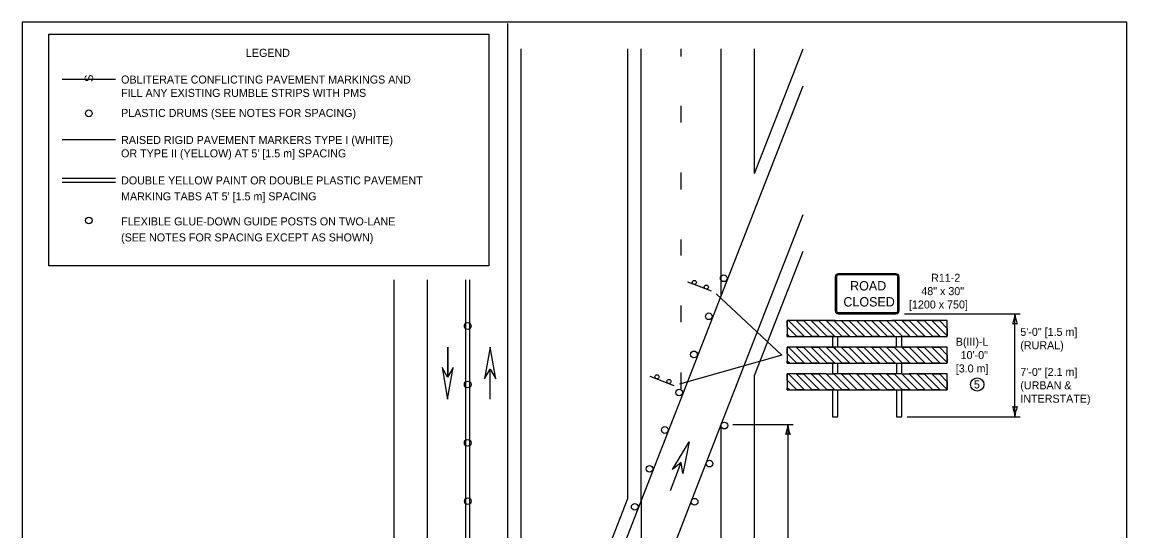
# Model space of a CAD drawing. Extents: x 49991.4 to 50021, y 49987.6 to 50011.4.
# Drawn here: x 50000.34 to 50008.61, y 50007.45 to 50011.26 of the extents above; entities that cross this region are included whole.
import ezdxf

# ---------------------------------------------------------------- set-up
doc = ezdxf.new("R2010")
doc.units = 0
for name, color, linetype in [('Level 1', 7, 'Continuous'), ('Level 2', 7, 'Continuous'), ('Level 3', 7, 'Continuous')]:
    doc.layers.add(name, color=color, linetype=linetype)

msp = doc.modelspace()

# ---------------------------------------------------------------- linework, layer by layer
at = {"layer": 'Level 1'}
for p, q in [((50003.9747, 50005.1129), (50003.9747, 50011.2528)), ((50004.0747, 50005.6442), (50004.0747, 50011.0628)), ((50004.8747, 50007.6956), (50004.8747, 50011.0628)), ((50004.9747, 50007.6763), (50004.9747, 50011.0628)), ((50005.2747, 50011.0059), (50005.2747, 50011.0628)), ((50005.5747, 50009.2143), (50005.5747, 50011.0628)), ((50005.8247, 50010.1303), (50005.8247, 50011.0628)), ((50005.8247, 50010.1303), (50006.1881, 50011.0617)), ((50001.0367, 50010.8335), (50000.6356, 50010.8335)), ((50005.5747, 50009.2143), (50006.1881, 50010.7865)), ((50005.2747, 50010.5108), (50005.2747, 50010.6358)), ((50001.0367, 50010.3818), (50000.6356, 50010.3818)), ((50005.2747, 50010.0108), (50005.2747, 50010.1358)), ((50001.0367, 50010.0915), (50000.6356, 50010.0915)), ((50001.0367, 50010.0615), (50000.6356, 50010.0615)), ((50005.5747, 50008.2511), (50006.1881, 50009.8235)), ((50005.2747, 50009.5158), (50005.2747, 50009.6358)), ((50005.8247, 50008.6168), (50006.1881, 50009.5483)), ((50003.1247, 50002.2265), (50003.1247, 50009.3328)), ((50003.3747, 50002.2265), (50003.3747, 50009.3328)), ((50003.6597, 50002.2708), (50003.6597, 50009.3328)), ((50003.6897, 50002.1862), (50003.6897, 50009.3328)), ((50005.4127, 50009.2823), (50005.3233, 50009.3171)), ((50006.4286, 50009.3563), (50006.4286, 50009.1013)), ((50006.4386, 50009.3563), (50006.4386, 50009.1013)), ((50006.8836, 50009.3788), (50006.4536, 50009.3788)), ((50006.8836, 50009.3698), (50006.4536, 50009.3698)), ((50006.8986, 50009.1013), (50006.8986, 50009.3563)), ((50006.9086, 50009.1013), (50006.9086, 50009.3563)), ((50005.5022, 50009.2474), (50005.4127, 50009.2823)), ((50003.9747, 50005.1129), (50005.5747, 50009.2143)), ((50005.2747, 50009.0158), (50005.2747, 50009.1408)), ((50006.4536, 50009.0878), (50006.8836, 50009.0878)), ((50006.4536, 50009.0788), (50006.8836, 50009.0788)), ((50006.1419, 50008.9088), (50006.0686, 50008.9821)), ((50006.1419, 50008.9088), (50006.0686, 50008.9821)), ((50006.1984, 50008.9088), (50006.0784, 50009.0288)), ((50006.0784, 50009.0288), (50006.1984, 50008.9088)), ((50006.255, 50008.9088), (50006.135, 50009.0288)), ((50006.255, 50008.9088), (50006.135, 50009.0288)), ((50006.3116, 50008.9088), (50006.1916, 50009.0288)), ((50006.1916, 50009.0288), (50006.3116, 50008.9088)), ((50006.3681, 50008.9088), (50006.2481, 50009.0288)), ((50006.3681, 50008.9088), (50006.2481, 50009.0288)), ((50006.4247, 50008.9088), (50006.3047, 50009.0288)), ((50006.3047, 50009.0288), (50006.4247, 50008.9088)), ((50006.4813, 50008.9088), (50006.3613, 50009.0288)), ((50006.5378, 50008.9088), (50006.4178, 50009.0288)), ((50006.4178, 50009.0288), (50006.4878, 50009.0288)), ((50006.4536, 50009.0288), (50006.8836, 50009.0288)), ((50006.5943, 50008.9088), (50006.4743, 50009.0288)), ((50006.6508, 50008.9088), (50006.5308, 50009.0288)), ((50006.7073, 50008.9088), (50006.5873, 50009.0288)), ((50006.7638, 50008.9088), (50006.6438, 50009.0288)), ((50006.8203, 50008.9088), (50006.7003, 50009.0288)), ((50006.8768, 50008.9088), (50006.7568, 50009.0288)), ((50006.9337, 50008.9088), (50006.8137, 50009.0288)), ((50006.9086, 50009.0288), (50006.8537, 50009.0288)), ((50006.9903, 50008.9088), (50006.8703, 50009.0288)), ((50007.0469, 50008.9088), (50006.9269, 50009.0288)), ((50007.0469, 50008.9088), (50006.9269, 50009.0288)), ((50007.1034, 50008.9088), (50006.9834, 50009.0288)), ((50006.9834, 50009.0288), (50007.1034, 50008.9088)), ((50007.16, 50008.9088), (50007.04, 50009.0288)), ((50007.16, 50008.9088), (50007.04, 50009.0288)), ((50007.2165, 50008.9088), (50007.0965, 50009.0288)), ((50007.0965, 50009.0288), (50007.2165, 50008.9088)), ((50007.2686, 50008.9133), (50007.1531, 50009.0288)), ((50007.2686, 50008.9133), (50007.1531, 50009.0288)), ((50007.2686, 50008.9699), (50007.2097, 50009.0288)), ((50007.2097, 50009.0288), (50007.2686, 50008.9699)), ((50006.0853, 50008.9088), (50006.0686, 50008.9255)), ((50006.0686, 50008.9255), (50006.0853, 50008.9088)), ((50006.4486, 50008.8289), (50006.4486, 50008.9088)), ((50006.8886, 50008.8289), (50006.8886, 50008.9088)), ((50003.5245, 50008.8303), (50003.5245, 50008.6045)), ((50003.5247, 50008.8303), (50003.5247, 50008.6045)), ((50006.1984, 50008.7089), (50006.0784, 50008.8289)), ((50006.0784, 50008.8289), (50006.1984, 50008.7089)), ((50006.255, 50008.7089), (50006.135, 50008.8289)), ((50006.255, 50008.7089), (50006.135, 50008.8289)), ((50006.3116, 50008.7089), (50006.1916, 50008.8289)), ((50006.1916, 50008.8289), (50006.3116, 50008.7089)), ((50006.3681, 50008.7089), (50006.2481, 50008.8289)), ((50006.3681, 50008.7089), (50006.2481, 50008.8289)), ((50006.4247, 50008.7089), (50006.3047, 50008.8289)), ((50006.3047, 50008.8289), (50006.4247, 50008.7089)), ((50006.4286, 50008.7616), (50006.3613, 50008.8289)), ((50006.4286, 50008.8181), (50006.4178, 50008.8289)), ((50006.5378, 50008.7089), (50006.4286, 50008.8181)), ((50006.5944, 50008.7089), (50006.4744, 50008.8289)), ((50006.6509, 50008.7089), (50006.5309, 50008.8289)), ((50006.7075, 50008.7089), (50006.5875, 50008.8289)), ((50006.7641, 50008.7089), (50006.6441, 50008.8289)), ((50006.8206, 50008.7089), (50006.7006, 50008.8289)), ((50006.8772, 50008.7089), (50006.7572, 50008.8289)), ((50006.9337, 50008.7089), (50006.8137, 50008.8289)), ((50006.9903, 50008.7089), (50006.8703, 50008.8289)), ((50007.0469, 50008.7089), (50006.9269, 50008.8289)), ((50007.0469, 50008.7089), (50006.9269, 50008.8289)), ((50007.1034, 50008.7089), (50006.9834, 50008.8289)), ((50006.9834, 50008.8289), (50007.1034, 50008.7089)), ((50007.16, 50008.7089), (50007.04, 50008.8289)), ((50007.16, 50008.7089), (50007.04, 50008.8289)), ((50007.2165, 50008.7089), (50007.0965, 50008.8289)), ((50007.0965, 50008.8289), (50007.2165, 50008.7089)), ((50007.2686, 50008.7134), (50007.1531, 50008.8289)), ((50007.2686, 50008.7134), (50007.1531, 50008.8289)), ((50007.2686, 50008.7699), (50007.2097, 50008.8289)), ((50007.2097, 50008.8289), (50007.2686, 50008.7699)), ((50006.1419, 50008.7089), (50006.0686, 50008.7821)), ((50006.1419, 50008.7089), (50006.0686, 50008.7821)), ((50006.0853, 50008.7089), (50006.0686, 50008.7256)), ((50006.0686, 50008.7256), (50006.0853, 50008.7089)), ((50006.4813, 50008.7089), (50006.4286, 50008.7616)), ((50003.8426, 50008.439), (50003.8426, 50008.6648)), ((50003.8428, 50008.439), (50003.8428, 50008.6648)), ((50005.2747, 50008.5157), (50005.2747, 50008.6408)), ((50005.1328, 50008.5759), (50005.0433, 50008.6108)), ((50005.2222, 50008.5411), (50005.1328, 50008.5759)), ((50005.8247, 50000.6846), (50005.8247, 50008.6168)), ((50006.1419, 50008.509), (50006.0686, 50008.5822)), ((50006.1419, 50008.509), (50006.0686, 50008.5822)), ((50006.1984, 50008.509), (50006.0784, 50008.629)), ((50006.0784, 50008.629), (50006.1984, 50008.509)), ((50006.255, 50008.509), (50006.135, 50008.629)), ((50006.255, 50008.509), (50006.135, 50008.629)), ((50006.3116, 50008.509), (50006.1916, 50008.629)), ((50006.1916, 50008.629), (50006.3116, 50008.509)), ((50006.3681, 50008.509), (50006.2481, 50008.629)), ((50006.3681, 50008.509), (50006.2481, 50008.629)), ((50006.4247, 50008.509), (50006.3047, 50008.629)), ((50006.3047, 50008.629), (50006.4247, 50008.509)), ((50006.4813, 50008.509), (50006.3613, 50008.629)), ((50006.4813, 50008.509), (50006.3613, 50008.629)), ((50006.5378, 50008.509), (50006.4178, 50008.629)), ((50006.4178, 50008.629), (50006.5378, 50008.509)), ((50006.5944, 50008.509), (50006.4744, 50008.629)), ((50006.5944, 50008.509), (50006.4744, 50008.629)), ((50006.6509, 50008.509), (50006.5309, 50008.629)), ((50006.5309, 50008.629), (50006.6509, 50008.509)), ((50006.7075, 50008.509), (50006.5875, 50008.629)), ((50006.7075, 50008.509), (50006.5875, 50008.629)), ((50006.7641, 50008.509), (50006.6441, 50008.629)), ((50006.6441, 50008.629), (50006.7641, 50008.509)), ((50006.8206, 50008.509), (50006.7006, 50008.629)), ((50006.8206, 50008.509), (50006.7006, 50008.629)), ((50006.8772, 50008.509), (50006.7572, 50008.629)), ((50006.7572, 50008.629), (50006.8772, 50008.509)), ((50006.9337, 50008.509), (50006.8137, 50008.629)), ((50006.9337, 50008.509), (50006.8137, 50008.629)), ((50006.9903, 50008.509), (50006.8703, 50008.629)), ((50006.8703, 50008.629), (50006.9903, 50008.509)), ((50007.0469, 50008.509), (50006.9269, 50008.629)), ((50007.0469, 50008.509), (50006.9269, 50008.629)), ((50007.1034, 50008.509), (50006.9834, 50008.629)), ((50006.9834, 50008.629), (50007.1034, 50008.509)), ((50007.16, 50008.509), (50007.04, 50008.629)), ((50007.16, 50008.509), (50007.04, 50008.629)), ((50007.2165, 50008.509), (50007.0965, 50008.629)), ((50007.0965, 50008.629), (50007.2165, 50008.509)), ((50007.2686, 50008.5134), (50007.1531, 50008.629)), ((50007.2686, 50008.5134), (50007.1531, 50008.629)), ((50007.2686, 50008.57), (50007.2097, 50008.629)), ((50007.2097, 50008.629), (50007.2686, 50008.57)), ((50006.0853, 50008.509), (50006.0686, 50008.5257)), ((50006.0686, 50008.5257), (50006.0853, 50008.509)), ((50003.9747, 50004.1495), (50005.5747, 50008.2511)), ((50005.5747, 50000.6846), (50005.5747, 50008.2511)), ((50005.1935, 50007.7556), (50005.2749, 50007.9669)), ((50005.1937, 50007.7557), (50005.2751, 50007.9668)), ((50004.0747, 50005.6442), (50004.8747, 50007.6956)), ((50004.9747, 50007.6763), (50004.9747, 50006.713))]:
    msp.add_line(p, q, dxfattribs=at)
for points in [[(50008.6146, 50011.2628), (50000.3356, 50011.2628), (50000.3356, 50000.0624), (50008.6146, 50000.0624)], [(50003.8846, 50008.5926), (50003.8428, 50008.829), (50003.801, 50008.5926), (50003.8428, 50008.6646)], [(50003.4827, 50008.6767), (50003.5245, 50008.4403), (50003.5663, 50008.6767), (50003.5245, 50008.6047)], [(50005.2097, 50007.914), (50005.3333, 50008.1198), (50005.2875, 50007.8843), (50005.2748, 50007.9667)]]:
    msp.add_lwpolyline(points, close=True, dxfattribs=at)
for points in [[(50006.4286, 50009.0288), (50006.0686, 50009.0288), (50006.0686, 50008.9088), (50006.4286, 50008.9088)], [(50006.0686, 50008.9821), (50006.0686, 50009.0288), (50006.0784, 50009.0288)], [(50006.135, 50009.0288), (50006.1916, 50009.0288)], [(50006.2481, 50009.0288), (50006.3047, 50009.0288)], [(50006.5378, 50008.9088), (50006.4813, 50008.9088), (50006.3613, 50009.0288), (50006.4178, 50009.0288), (50006.5378, 50008.9088)], [(50006.4286, 50008.9088), (50007.2686, 50008.9088), (50007.2686, 50009.0288), (50006.9086, 50009.0288)], [(50006.4743, 50009.0288), (50006.4878, 50009.0288), (50006.5308, 50009.0288), (50006.6508, 50008.9088), (50006.5943, 50008.9088), (50006.4743, 50009.0288)], [(50006.5873, 50009.0288), (50006.6438, 50009.0288), (50006.7638, 50008.9088), (50006.7073, 50008.9088), (50006.5873, 50009.0288)], [(50006.7003, 50009.0288), (50006.7568, 50009.0288), (50006.8768, 50008.9088), (50006.8203, 50008.9088), (50006.7003, 50009.0288)], [(50006.8137, 50009.0288), (50006.8537, 50009.0288), (50006.8703, 50009.0288), (50006.9903, 50008.9088), (50006.9337, 50008.9088), (50006.8137, 50009.0288)], [(50006.9269, 50009.0288), (50006.9834, 50009.0288)], [(50007.04, 50009.0288), (50007.0965, 50009.0288)], [(50007.1531, 50009.0288), (50007.2097, 50009.0288)], [(50007.2686, 50008.9699), (50007.2686, 50008.9133)], [(50006.0853, 50008.9088), (50006.0686, 50008.9088), (50006.0686, 50008.9255)], [(50006.1984, 50008.9088), (50006.1419, 50008.9088)], [(50006.3116, 50008.9088), (50006.255, 50008.9088)], [(50006.4247, 50008.9088), (50006.3681, 50008.9088)], [(50006.4086, 50008.9088), (50006.4086, 50008.8289)], [(50006.9286, 50008.8288), (50006.9286, 50008.9088)], [(50007.1034, 50008.9088), (50007.0469, 50008.9088)], [(50007.2165, 50008.9088), (50007.16, 50008.9088)], [(50006.4286, 50008.8289), (50006.0686, 50008.8289), (50006.0686, 50008.7089), (50007.2686, 50008.7089), (50007.2686, 50008.8289), (50006.4286, 50008.8289)], [(50006.0686, 50008.7821), (50006.0686, 50008.8289), (50006.0784, 50008.8289)], [(50006.135, 50008.8289), (50006.1916, 50008.8289)], [(50006.2481, 50008.8289), (50006.3047, 50008.8289)], [(50006.5378, 50008.7089), (50006.4813, 50008.7089), (50006.4286, 50008.7616), (50006.3613, 50008.8289), (50006.4086, 50008.8289), (50006.4178, 50008.8289), (50006.4286, 50008.8181), (50006.5378, 50008.7089)], [(50006.4744, 50008.8289), (50006.5309, 50008.8289), (50006.6509, 50008.7089), (50006.5944, 50008.7089), (50006.4744, 50008.8289)], [(50006.5875, 50008.8289), (50006.6441, 50008.8289), (50006.7641, 50008.7089), (50006.7075, 50008.7089), (50006.5875, 50008.8289)], [(50006.7006, 50008.8289), (50006.7572, 50008.8289), (50006.8772, 50008.7089), (50006.8206, 50008.7089), (50006.7006, 50008.8289)], [(50006.8137, 50008.8289), (50006.8703, 50008.8289), (50006.9903, 50008.7089), (50006.9337, 50008.7089), (50006.8137, 50008.8289)], [(50006.9269, 50008.8289), (50006.9834, 50008.8289)], [(50007.04, 50008.8289), (50007.0965, 50008.8289)], [(50007.1531, 50008.8289), (50007.2097, 50008.8289)], [(50006.0853, 50008.7089), (50006.0686, 50008.7089), (50006.0686, 50008.7256)], [(50007.2686, 50008.7699), (50007.2686, 50008.7134)], [(50006.1984, 50008.7089), (50006.1419, 50008.7089)], [(50006.3116, 50008.7089), (50006.255, 50008.7089)], [(50006.4247, 50008.7089), (50006.3681, 50008.7089)], [(50006.4086, 50008.7089), (50006.4086, 50008.629)], [(50006.4486, 50008.629), (50006.4486, 50008.7089)], [(50006.8886, 50008.7089), (50006.8886, 50008.629)], [(50006.9286, 50008.629), (50006.9286, 50008.7089)], [(50007.1034, 50008.7089), (50007.0469, 50008.7089)], [(50007.2165, 50008.7089), (50007.16, 50008.7089)], [(50006.0686, 50008.5822), (50006.0686, 50008.629), (50006.0784, 50008.629)], [(50006.3613, 50008.629), (50006.0686, 50008.629), (50006.0686, 50008.509), (50007.2686, 50008.509), (50007.2686, 50008.629), (50006.9834, 50008.629)], [(50006.135, 50008.629), (50006.1916, 50008.629)], [(50006.2481, 50008.629), (50006.3047, 50008.629)], [(50006.3613, 50008.629), (50006.4178, 50008.629)], [(50006.9269, 50008.629), (50006.4178, 50008.629)], [(50006.4744, 50008.629), (50006.5309, 50008.629)], [(50006.5875, 50008.629), (50006.6441, 50008.629)], [(50006.7006, 50008.629), (50006.7572, 50008.629)], [(50006.8137, 50008.629), (50006.8703, 50008.629)], [(50006.9269, 50008.629), (50006.9834, 50008.629)], [(50007.04, 50008.629), (50007.0965, 50008.629)], [(50007.1531, 50008.629), (50007.2097, 50008.629)], [(50007.2686, 50008.57), (50007.2686, 50008.5134)], [(50006.0853, 50008.509), (50006.0686, 50008.509), (50006.0686, 50008.5257)], [(50006.1984, 50008.509), (50006.1419, 50008.509)], [(50006.3116, 50008.509), (50006.255, 50008.509)], [(50006.4247, 50008.509), (50006.3681, 50008.509)], [(50006.4086, 50008.5088), (50006.4086, 50008.3088), (50006.4486, 50008.3088), (50006.4486, 50008.5088)], [(50006.5378, 50008.509), (50006.4813, 50008.509)], [(50006.6509, 50008.509), (50006.5944, 50008.509)], [(50006.7641, 50008.509), (50006.7075, 50008.509)], [(50006.8772, 50008.509), (50006.8206, 50008.509)], [(50006.8886, 50008.5088), (50006.8886, 50008.3088), (50006.9286, 50008.3088), (50006.9286, 50008.5088)], [(50006.9903, 50008.509), (50006.9337, 50008.509)], [(50007.1034, 50008.509), (50007.0469, 50008.509)], [(50007.2165, 50008.509), (50007.16, 50008.509)]]:
    msp.add_lwpolyline(points, dxfattribs=at)
for centre, radius in [((50000.836, 50010.5799), 0.025), ((50000.836, 50009.7771), 0.025), ((50005.3737, 50009.3138), 0.0152), ((50005.5932, 50009.3449), 0.025), ((50005.4631, 50009.279), 0.0152), ((50005.4816, 50009.0603), 0.025), ((50003.6746, 50008.9878), 0.025), ((50005.3705, 50008.7753), 0.025), ((50003.6746, 50008.5503), 0.025), ((50005.0933, 50008.6073), 0.0152), ((50005.1828, 50008.5725), 0.0152), ((50005.2593, 50008.4903), 0.025), ((50005.1516, 50008.2092), 0.025), ((50005.598, 50008.242), 0.025), ((50003.6746, 50008.1128), 0.025), ((50005.4864, 50007.9574), 0.025), ((50005.0377, 50007.9189), 0.025), ((50003.6751, 50007.6761), 0.025), ((50004.9265, 50007.6338), 0.025), ((50005.3752, 50007.6724), 0.025)]:
    msp.add_circle(centre, radius, dxfattribs=at)
for centre, major_axis, start_param, end_param in [((50006.4536, 50009.3563), (-0.025, 0), 4.712389, 6.283185), ((50006.4536, 50009.3563), (-0.015, 0), 4.712389, 6.283185), ((50006.8836, 50009.3563), (0.025, 0), 0, 1.570796), ((50006.8836, 50009.3563), (0.015, 0), 0, 1.570796), ((50006.4536, 50009.1013), (-0.025, 0), 0, 1.570796), ((50006.4536, 50009.1013), (-0.015, 0), 0, 1.570796), ((50006.8836, 50009.1013), (0.025, 0), 4.712389, 6.283185), ((50006.8836, 50009.1013), (0.015, 0), 4.712389, 6.283185)]:
    msp.add_ellipse(centre, major_axis=major_axis, ratio=0.9, start_param=start_param, end_param=end_param, dxfattribs=at)
at = {"layer": 'Level 2'}
for p, q in [((50000.5356, 50009.4371), (50000.5356, 50011.1722)), ((50000.5356, 50011.1722), (50003.833, 50011.1722)), ((50003.833, 50011.1722), (50003.833, 50009.4371)), ((50003.833, 50009.4371), (50000.5356, 50009.4371))]:
    msp.add_line(p, q, dxfattribs=at)
msp.add_circle((50007.4929, 50008.5499), 0.05, dxfattribs=at)
at = {"layer": 'Level 3'}
for p, q in [((50005.5377, 50009.2289), (50006.0286, 50008.7689)), ((50006.9486, 50009.0788), (50007.816, 50009.0788)), ((50007.776, 50008.3088), (50007.776, 50009.0788)), ((50006.0286, 50008.7689), (50005.2608, 50008.5517)), ((50006.9686, 50008.3088), (50007.816, 50008.3088)), ((50005.6613, 50008.2511), (50006.1147, 50008.2511)), ((50006.0747, 50008.2511), (50006.0747, 50008.026)), ((50006.0747, 50008.026), (50006.0747, 50007.5199)), ((50006.0747, 50007.5199), (50006.0747, 50006.6372))]:
    msp.add_line(p, q, dxfattribs=at)
for centre, radius, start, end in [((50007.5539, 50009.0879), 0.2223, 337.45601, 357.63952), ((50008.0087, 50009.0902), 0.233, 182.82731, 202.07716), ((50007.776, 50008.9505), 0.0548, 72.13882, 107.86118), ((50007.776, 50008.437), 0.0548, 252.13882, 287.86118), ((50007.5433, 50008.2973), 0.233, 2.82731, 22.07716), ((50007.9981, 50008.2996), 0.2223, 157.45601, 177.63952), ((50005.842, 50008.2626), 0.233, 337.92284, 357.17269), ((50006.2969, 50008.2603), 0.2223, 182.36048, 202.54399), ((50006.0747, 50008.1229), 0.0548, 72.13882, 107.86118)]:
    msp.add_arc(centre, radius, start, end, dxfattribs=at)

# ---------------------------------------------------------------- texts
at = {"layer": 'Level 1'}
msp.add_text('S', height=0.0625, rotation=90, dxfattribs=at).set_placement((50000.8674, 50010.8143))
for s, p in [('ROAD', (50006.5405, 50009.2538)), ('CLOSED', (50006.4903, 50009.1338))]:
    msp.add_text(s, height=0.07, dxfattribs=at).set_placement(p)
at = {"layer": 'Level 2'}
for s, p in [('LEGEND', (50002.0127, 50011.0028)), ('OBLITERATE CONFLICTING PAVEMENT MARKINGS AND ', (50001.0775, 50010.8028)), ('FILL ANY EXISTING RUMBLE STRIPS WITH PMS', (50001.0775, 50010.7028)), ('PLASTIC DRUMS (SEE NOTES FOR SPACING)', (50001.0775, 50010.5528)), ('RAISED RIGID PAVEMENT MARKERS TYPE I (WHITE) ', (50001.0775, 50010.3503)), ("OR TYPE II (YELLOW) AT 5' [1.5 m] SPACING", (50001.0775, 50010.2503)), ('DOUBLE YELLOW PAINT OR DOUBLE PLASTIC PAVEMENT', (50001.0775, 50010.0477)), ("MARKING TABS AT 5' [1.5 m] SPACING", (50001.0775, 50009.9285)), ('FLEXIBLE GLUE-DOWN GUIDE POSTS ON TWO-LANE', (50001.0775, 50009.7409)), ('(SEE NOTES FOR SPACING EXCEPT AS SHOWN)', (50001.0775, 50009.6209)), ('R11-2', (50007.1473, 50009.3188)), ('48" x 30"', (50007.0741, 50009.2188)), ('[1200 x 750]', (50006.9816, 50009.1188)), ('5\'-0" [1.5 m]', (50007.816, 50008.9138)), ('B(III)-L', (50007.3322, 50008.8399)), ('(RURAL)', (50007.816, 50008.8138)), (' 10\'-0"', (50007.3464, 50008.7399)), ('[3.0 m]', (50007.3322, 50008.6399)), ('7\'-0" [2.1 m]', (50007.816, 50008.6138)), ('5', (50007.468, 50008.5201)), ('(URBAN &', (50007.816, 50008.5138)), ('INTERSTATE)', (50007.816, 50008.4138))]:
    msp.add_text(s, height=0.06, dxfattribs=at).set_placement(p)

doc.saveas('drawing.dxf')
